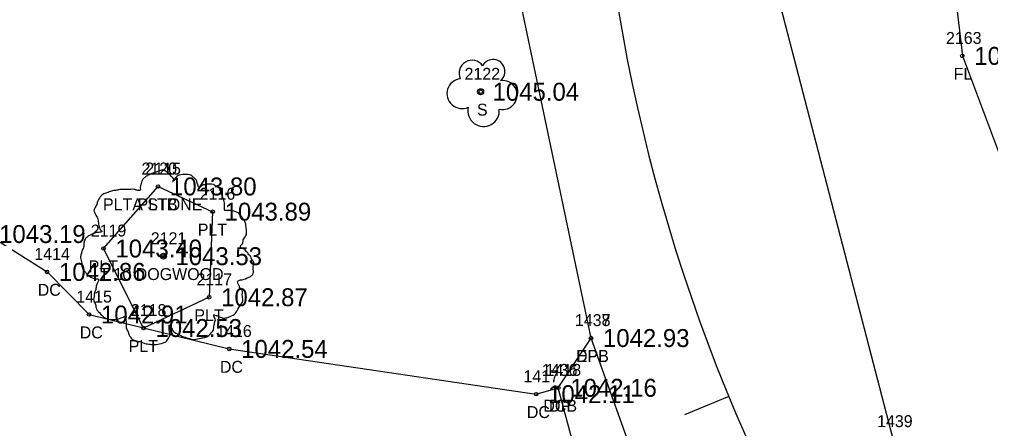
# Model space of a CAD drawing. Extents: x 1578957 to 1581675, y 1115963 to 1120391.
# Drawn here: x 1579731.3 to 1579812.6, y 1117803.6 to 1117837.9 of the extents above; entities that cross this region are included whole.
import ezdxf

# ---------------------------------------------------------------- set-up
doc = ezdxf.new("R2010")
doc.units = 0
for name, color, linetype in [('RD_EX_BldgApp', 7, 'Continuous'), ('RD_EX_BldgApp_txCode', 7, 'Continuous'), ('RD_EX_Conc', 7, 'Continuous'), ('RD_EX_Conc_txCode', 7, 'Continuous'), ('RD_EX_Driveway', 7, 'Continuous'), ('RD_EX_Driveway_txCode', 7, 'Continuous'), ('RD_EX_Fence_Other', 7, 'Continuous'), ('RD_EX_Fence_Other_txCode', 7, 'Continuous'), ('RD_EX_Road', 7, 'Continuous'), ('RD_EX_Road_txCode', 7, 'Continuous'), ('RD_EX_TX_BldgApp_ELEV', 7, 'Continuous'), ('RD_EX_TX_Conc_ELEV', 7, 'Continuous'), ('RD_EX_TX_Driveway_ELEV', 7, 'Continuous'), ('RD_EX_TX_Fence_Other_ELEV', 7, 'Continuous'), ('RD_EX_TX_Road_ELEV', 7, 'Continuous'), ('RD_EX_TX_VEG_ELEV', 7, 'Continuous'), ('RD_EX_VEG', 7, 'Continuous'), ('RD_EX_VEG_txCode', 7, 'Continuous'), ('RD_HC_Cl', 7, 'Continuous'), ('RD_HC_Data_Tic', 7, 'Continuous'), ('RD_SMD_Locator', 7, 'Continuous')]:
    doc.layers.add(name, color=color, linetype=linetype)

msp = doc.modelspace()

# ---------------------------------------------------------------- linework, layer by layer
at = {"layer": 'RD_EX_BldgApp'}
msp.add_lwpolyline([(1579742.865, 1117823.873), (1579747.437, 1117821.763), (1579747.148, 1117814.598), (1579741.65, 1117812.021), (1579738.294, 1117818.679), (1579742.865, 1117823.873)], dxfattribs=at)
at = {"layer": 'RD_EX_Conc'}
msp.add_lwpolyline([(1579703.598, 1117820.153), (1579728.553, 1117819.89), (1579733.569, 1117816.721), (1579737.087, 1117813.155), (1579748.821, 1117810.274), (1579774.526, 1117806.485), (1579776.381, 1117807.018)], dxfattribs=at)
at = {"layer": 'RD_EX_Driveway'}
msp.add_lwpolyline([(1579787.439, 1117787.947), (1579783.574, 1117792.119), (1579779.975, 1117793.644), (1579776.381, 1117807.018), (1579779.119, 1117811.184)], dxfattribs=at)
at = {"layer": 'RD_EX_Fence_Other'}
msp.add_lwpolyline([(1579823.104, 1118041.087), (1579819.64, 1117977.762), (1579811.21, 1117936.274), (1579806.912, 1117888.201), (1579805.65, 1117872.977), (1579810.216, 1117834.804), (1579821.355, 1117805.105), (1579835.234, 1117784.194), (1579851.403, 1117768.05), (1579868.554, 1117757.557), (1579908.33, 1117744.227), (1579949.735, 1117742.637), (1579998.853, 1117745.107), (1580033.637, 1117749.157), (1580057.075, 1117744.228), (1580092.078, 1117730.794), (1580117.524, 1117724.619), (1580141.715, 1117727.925), (1580159.983, 1117735.31), (1580192.445, 1117760.446), (1580226.972, 1117787.769), (1580271.309, 1117822.486), (1580302.096, 1117858.032)], dxfattribs=at)
at = {"layer": 'RD_EX_Road'}
for points in [[(1580132.914, 1117689.949), (1580126.197, 1117690.713), (1580104.514, 1117701.773), (1580054.231, 1117722.915), (1579999.655, 1117728.645), (1579947.034, 1117725.641), (1579902.617, 1117727.901), (1579859.282, 1117741.23), (1579828.335, 1117764.868), (1579804.422, 1117802.726), (1579793.197, 1117845.912), (1579792.758, 1117891.982), (1579799.628, 1117938.215), (1579807.414, 1117987.508), (1579809.684, 1118039.768), (1579804.464, 1118093.359), (1579794.793, 1118143.944)], [(1580121.995, 1117647.598), (1580119.902, 1117658.172), (1580108.554, 1117670.894), (1580093.888, 1117680.496), (1580047.657, 1117700.115), (1579998.943, 1117706.513), (1579949.017, 1117704.446), (1579899.181, 1117706.754), (1579851.312, 1117721.596), (1579810.789, 1117752.923), (1579804.028, 1117759.706), (1579792.304, 1117778.187), (1579787.439, 1117787.947), (1579779.119, 1117811.184), (1579772.603, 1117842.297), (1579771.808, 1117848.588), (1579770.145, 1117878.236), (1579771.725, 1117892.019), (1579778.922, 1117940.842), (1579785.853, 1117982.888), (1579786.73, 1117990.339), (1579789.156, 1118040.245), (1579783.452, 1118089.738), (1579774.288, 1118139.394)]]:
    msp.add_lwpolyline(points, dxfattribs=at)
at = {"layer": 'RD_EX_VEG'}
for centre, radius in [((1579769.875, 1117831.803), 0.25), ((1579743.319, 1117818.038), 0.25), ((1579743.307, 1117818.019), 0.0001)]:
    msp.add_circle(centre, radius, dxfattribs=at)
for centre, radius, start, end in [((1579769.154, 1117833.351), 1.084, 34.97629, 204.75602), ((1579770.921, 1117833.505), 0.995, 308.76261, 152.04674), ((1579768.312, 1117831.648), 1.257, 96.45179, 294.73401), ((1579771.715, 1117831.524), 1.218, 256.56668, 98.10463), ((1579770.121, 1117830.207), 1.318, 166.88266, 5.75893)]:
    msp.add_arc(centre, radius, start, end, dxfattribs=at)
for points in [[(1579743.451, 1117825.205), (1579743.151, 1117825.23), (1579742.826, 1117825.13), (1579742.577, 1117825.03), (1579742.352, 1117824.955), (1579742.127, 1117824.855), (1579741.827, 1117824.681), (1579741.602, 1117824.481), (1579741.477, 1117824.231), (1579741.427, 1117824.006), (1579741.377, 1117823.731), (1579741.377, 1117823.556), (1579741.252, 1117823.531), (1579741.102, 1117823.556), (1579740.852, 1117823.631), (1579740.602, 1117823.631), (1579740.352, 1117823.631), (1579740.003, 1117823.606), (1579739.653, 1117823.606), (1579739.378, 1117823.556), (1579739.053, 1117823.506), (1579738.678, 1117823.381), (1579738.328, 1117823.256), (1579738.029, 1117823.006), (1579737.779, 1117822.532), (1579737.654, 1117822.182), (1579737.504, 1117821.932), (1579737.654, 1117821.482), (1579737.829, 1117821.132), (1579737.854, 1117820.932), (1579737.929, 1117820.507), (1579738.029, 1117820.283), (1579738.153, 1117820.083), (1579738.079, 1117820.058), (1579737.704, 1117820.008), (1579737.404, 1117819.908), (1579736.979, 1117819.683), (1579736.754, 1117819.458), (1579736.654, 1117819.133), (1579736.629, 1117818.783), (1579736.529, 1117818.583), (1579736.454, 1117818.308), (1579736.429, 1117818.233), (1579736.379, 1117817.909), (1579736.479, 1117817.459), (1579736.504, 1117817.109), (1579736.629, 1117816.884), (1579736.779, 1117816.709), (1579736.954, 1117816.459), (1579737.354, 1117816.234), (1579737.679, 1117816.134), (1579737.879, 1117816.109), (1579737.704, 1117815.61), (1579737.654, 1117815.26), (1579737.529, 1117814.86), (1579737.529, 1117814.785), (1579737.479, 1117814.31), (1579737.629, 1117813.985), (1579737.704, 1117813.61), (1579737.879, 1117813.386), (1579738.153, 1117813.086), (1579738.478, 1117812.861), (1579738.978, 1117812.736), (1579739.378, 1117812.761), (1579739.953, 1117812.936), (1579740.203, 1117813.011), (1579740.178, 1117812.836), (1579740.203, 1117812.461), (1579740.203, 1117812.036), (1579740.352, 1117811.711), (1579740.452, 1117811.436), (1579740.602, 1117811.186), (1579740.927, 1117810.962), (1579741.327, 1117810.887), (1579741.752, 1117810.737), (1579742.202, 1117810.662), (1579742.701, 1117810.637), (1579743.301, 1117810.787), (1579743.576, 1117810.912), (1579743.676, 1117811.087), (1579743.876, 1117811.461), (1579743.826, 1117811.686), (1579743.851, 1117812.286), (1579743.951, 1117812.111), (1579744.126, 1117811.761), (1579744.626, 1117811.461), (1579745.025, 1117811.286), (1579745.5, 1117811.136), (1579745.8, 1117811.062), (1579746.275, 1117811.136), (1579746.65, 1117811.211), (1579747.025, 1117811.336), (1579747.324, 1117811.611), (1579747.499, 1117811.886), (1579747.549, 1117812.161), (1579747.624, 1117812.536), (1579747.674, 1117812.711)], [(1579747.674, 1117812.711), (1579747.599, 1117812.886), (1579747.549, 1117813.136), (1579747.624, 1117813.111), (1579747.799, 1117813.061), (1579748.074, 1117812.936), (1579748.299, 1117812.861), (1579748.624, 1117812.886), (1579748.899, 1117812.986), (1579749.349, 1117813.261), (1579749.623, 1117813.735), (1579749.898, 1117814.135), (1579749.973, 1117814.46), (1579749.923, 1117814.685), (1579749.898, 1117815.185), (1579749.698, 1117815.435), (1579749.648, 1117815.56), (1579749.548, 1117815.959), (1579749.623, 1117816.009), (1579749.898, 1117816.059), (1579750.273, 1117816.184), (1579750.548, 1117816.309), (1579750.773, 1117816.484), (1579750.848, 1117816.709), (1579750.823, 1117817.109), (1579750.873, 1117817.509), (1579750.798, 1117817.659), (1579750.698, 1117817.809), (1579750.623, 1117818.009), (1579750.473, 1117818.158), (1579750.373, 1117818.308), (1579750.273, 1117818.408), (1579750.148, 1117818.558), (1579749.973, 1117818.683), (1579749.823, 1117818.733), (1579749.773, 1117818.883), (1579749.923, 1117819.083), (1579749.973, 1117819.183), (1579749.998, 1117819.408), (1579750.223, 1117819.758), (1579750.273, 1117820.158), (1579750.223, 1117820.582), (1579750.173, 1117820.857), (1579750.023, 1117821.132), (1579749.823, 1117821.382), (1579749.698, 1117821.557), (1579749.523, 1117821.682), (1579749.199, 1117821.807), (1579748.949, 1117821.857), (1579748.599, 1117821.857), (1579748.399, 1117821.907), (1579748.424, 1117821.957), (1579748.424, 1117822.107), (1579748.424, 1117822.382), (1579748.349, 1117822.831), (1579748.199, 1117823.331), (1579748.199, 1117823.356), (1579748.099, 1117823.606), (1579747.874, 1117823.806), (1579747.699, 1117823.906), (1579747.499, 1117824.031), (1579747.249, 1117824.056), (1579746.95, 1117824.056), (1579746.675, 1117824.006), (1579746.475, 1117823.906), (1579746.3, 1117823.781), (1579746.225, 1117823.931), (1579746.125, 1117824.231), (1579746.075, 1117824.381), (1579745.925, 1117824.556), (1579745.7, 1117824.756), (1579745.25, 1117824.88), (1579744.626, 1117824.806), (1579744.326, 1117824.606), (1579744.176, 1117824.431), (1579744.126, 1117824.556), (1579743.926, 1117824.756), (1579743.826, 1117824.93), (1579743.651, 1117825.055), (1579743.501, 1117825.155), (1579743.401, 1117825.205)]]:
    msp.add_spline(points, degree=3, dxfattribs=at)
at = {"layer": 'RD_HC_Cl'}
msp.add_arc((1579928.874, 1117863.307), 149.519, 171.12359, 273.23235, dxfattribs=at)
at = {"layer": 'RD_HC_Data_Tic'}
msp.add_line((1579790.653, 1117806.289), (1579786.955, 1117804.763), dxfattribs=at)
at = {"layer": 'RD_SMD_Locator'}
for centre in [(1579810.216, 1117834.804), (1579769.875, 1117831.803), (1579742.865, 1117823.873), (1579742.865, 1117823.873), (1579747.437, 1117821.763), (1579738.294, 1117818.679), (1579743.319, 1117818.038), (1579733.569, 1117816.721), (1579747.148, 1117814.598), (1579737.087, 1117813.155), (1579741.65, 1117812.021), (1579779.119, 1117811.184), (1579779.119, 1117811.184), (1579748.821, 1117810.274), (1579776.381, 1117807.018), (1579776.381, 1117807.018), (1579774.526, 1117806.485)]:
    msp.add_circle(centre, 0.15, dxfattribs=at)

# ---------------------------------------------------------------- texts
at = {"layer": 'RD_EX_BldgApp_txCode'}
for s, p in [('2120', (1579741.479, 1117824.873)), ('2115', (1579741.802, 1117824.873)), ('2116', (1579746.351, 1117822.763)), ('PLTA STONE', (1579738.255, 1117821.873)), ('PLTB', (1579741.149, 1117821.873)), ('2119', (1579737.231, 1117819.679)), ('PLT', (1579746.193, 1117819.763)), ('PLT', (1579737.05, 1117816.679)), ('2117', (1579746.085, 1117815.598)), ('2118', (1579740.587, 1117813.021)), ('PLT', (1579745.904, 1117812.598)), ('PLT', (1579740.406, 1117810.021))]:
    msp.add_text(s, height=1, dxfattribs=at).set_placement(p)
at = {"layer": 'RD_EX_Conc_txCode'}
for s, p in [('1414', (1579732.506, 1117817.721)), ('DC', (1579732.789, 1117814.721)), ('1415', (1579736.024, 1117814.155)), ('DC', (1579736.307, 1117811.155)), ('1416', (1579747.734, 1117811.274)), ('DC', (1579748.041, 1117808.274)), ('1418', (1579775.318, 1117808.018)), ('1417', (1579773.463, 1117807.485)), ('DC', (1579773.746, 1117804.485)), ('DCB', (1579775.129, 1117805.018))]:
    msp.add_text(s, height=1, dxfattribs=at).set_placement(p)
at = {"layer": 'RD_EX_Driveway_txCode'}
for s, p in [('1437', (1579777.772, 1117812.184)), ('DPB', (1579777.867, 1117809.184)), ('1436', (1579775.011, 1117808.018)), ('DP', (1579775.601, 1117805.018))]:
    msp.add_text(s, height=1, dxfattribs=at).set_placement(p)
at = {"layer": 'RD_EX_Fence_Other_txCode'}
for s, p in [('2163', (1579808.846, 1117835.804)), ('FL', (1579809.484, 1117832.804))]:
    msp.add_text(s, height=1, dxfattribs=at).set_placement(p)
at = {"layer": 'RD_EX_Road_txCode'}
for s, p in [('1438', (1579777.772, 1117812.184)), ('EPL', (1579777.914, 1117809.184)), ('1439', (1579803.076, 1117803.726))]:
    msp.add_text(s, height=1, dxfattribs=at).set_placement(p)
at = {"layer": 'RD_EX_TX_BldgApp_ELEV'}
for s, p in [('1043.80', (1579743.865, 1117823.123)), ('1043.80', (1579743.865, 1117823.123)), ('1043.89', (1579748.437, 1117821.013)), ('1043.40', (1579739.294, 1117817.929)), ('1042.87', (1579748.148, 1117813.848)), ('1042.53', (1579742.65, 1117811.271))]:
    msp.add_text(s, height=1.5, dxfattribs=at).set_placement(p)
at = {"layer": 'RD_EX_TX_Conc_ELEV'}
for s, p in [('1043.19', (1579729.553, 1117819.14)), ('1042.86', (1579734.569, 1117815.971)), ('1042.91', (1579738.087, 1117812.405)), ('1042.54', (1579749.821, 1117809.524)), ('1042.11', (1579775.526, 1117805.735)), ('1042.16', (1579777.381, 1117806.268))]:
    msp.add_text(s, height=1.5, dxfattribs=at).set_placement(p)
at = {"layer": 'RD_EX_TX_Driveway_ELEV'}
for s, p in [('1042.93', (1579780.119, 1117810.434)), ('1042.16', (1579777.381, 1117806.268))]:
    msp.add_text(s, height=1.5, dxfattribs=at).set_placement(p)
at = {"layer": 'RD_EX_TX_Fence_Other_ELEV'}
msp.add_text('1046.02', height=1.5, dxfattribs=at).set_placement((1579811.216, 1117834.054))
at = {"layer": 'RD_EX_TX_Road_ELEV'}
msp.add_text('1042.93', height=1.5, dxfattribs=at).set_placement((1579780.119, 1117810.434))
at = {"layer": 'RD_EX_TX_VEG_ELEV'}
for s, p in [('1045.04', (1579770.875, 1117831.053)), ('1043.53', (1579744.319, 1117817.288))]:
    msp.add_text(s, height=1.5, dxfattribs=at).set_placement(p)
at = {"layer": 'RD_EX_VEG_txCode'}
for s, p in [('2122', (1579768.529, 1117832.803)), ('S', (1579769.568, 1117829.803)), ('2121', (1579742.256, 1117819.038)), ('T 10 DOGWOOD', (1579737.949, 1117816.038))]:
    msp.add_text(s, height=1, dxfattribs=at).set_placement(p)

doc.saveas('drawing.dxf')
